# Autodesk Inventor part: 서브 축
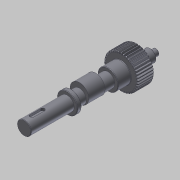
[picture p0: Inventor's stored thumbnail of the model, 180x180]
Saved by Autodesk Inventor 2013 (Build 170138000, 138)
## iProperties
Created: 2016-02
Part Number: 서브 축
Material: 강철, 연강
Document SubType Name: Modeling
Designer: mdu
Categories: <?xml version="1.0" encoding="UTF-16"?> <MemberInstance><Categories><FamilyTemplate><FamilyTemplateParameter ValueType="xs:double" Id="1" ObjectReferenceKey="da
Density: 7.86 g/cm^3
Mass: 504.229 g
Surface Area: 165.256 cm^2
Volume: 64.1513 cm^3
CustomPartVersion: 1
Author: mdu
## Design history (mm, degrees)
sketch "Sketch1"
  geometry: C1 r 21 at (0, 0)
  constraints: 1 centre point
  dimensions: "d0" = 42 diameter of C1 (= da_da)
extrude "Extrusion1" new body sketch "Sketch1" distance "d1" = 20 (= da_b); taper "d2" = 0 deg
workplane "Work Plane2"
feature "피치 지름" dims "d4" = 10, "d5" = 0
workplane "Work Plane8"
workplane "Work Plane9"
chamfer "모따기1" distance "d49" = 1; stored, may be unused: second distance "d50" = 2, angle "d51" = 45 deg
sketch "스케치3"
  geometry: C1 r 12.5 at (0, 0); 1 further point
  constraints: 1 centre point, 1 coincident
  dimensions: "d52" = 25 diameter of C1
extrude "돌출2" join sketch "스케치3" distance "d53" = 16; taper "d54" = 0 deg
sketch "스케치4"
  geometry: C1 r 8.5 at (0, 0); 1 further point
  constraints: 1 centre point, 1 coincident
  dimensions: "d55" = 17 diameter of C1
extrude "돌출3" join sketch "스케치4" distance "d56" = 103; taper "d57" = 0 deg
sketch "스케치5"
  geometry: C1 r 7.5 at (0, 0); 1 further point
  constraints: 1 centre point, 1 coincident
  dimensions: "d62" = 15 diameter of C1
extrude "돌출4" join sketch "스케치5" distance "d63" = 16; taper "d64" = 0 deg
sketch "스케치6"
  geometry: C1 r 4 at (0, 0); 1 further point
  constraints: 1 centre point, 1 coincident
  dimensions: "d65" = 8 diameter of C1
extrude "돌출5" join sketch "스케치6" distance "d66" = 7; taper "d67" = 0 deg
chamfer "모따기2" distance "d58" = 0.5; stored, may be unused: second distance "d59" = 2, angle "d60" = 45 deg
fillet "모깎기1" dims "d61" = 0.5
feature "스퍼 기어" dims "da_b" = 20, "da_d" = 40, "da_aw" = 31, "da_da" = 42, "da_df" = 37.5, "da_dw" = 40, angle "da_beta" = 0 deg, "da_lefttooth" = 0, "da_righttooth" = 0
node "작업 평면11"
sketch "스케치7"
  geometry: C1 r 8.5 at (0, 0) reference; C2 r 11.5 at (0, 3); 1 further point
  constraints: 1 centre point, 1 tangent, 1 vertical alignment
  dimensions: "d71" = 3 distance of C2.centre point (0, 0); "d72" = 23 diameter of C2 (derived)
extrude "돌출6" join sketch "스케치7" stored distance "d73" = 20; taper "d74" = 0 deg
node "작업 평면12"
sketch "스케치8"
  geometry: C1 r 12.5 at (0, 0) reference; 1 further point
extrude "돌출7" join sketch "스케치8" distance "d76" = 5; taper "d77" = 0 deg
chamfer "모따기3" distance "d78" = 0.5; stored, may be unused: second distance "d79" = 2, angle "d80" = 45 deg
sketch "스케치9"
  geometry: L1 (-8.5, 86)-(-8.5, 138.5) reference; L2 (-8, 139)-(8, 139) reference; L3 (0, 0)-(0, 139); L4 (-8.5, 115)-(0, 115); L5 (-8.5, 115)-(-8.5, 113.5); L6 (-7, 115)-(-8.5, 113.5)
  constraints: 8 end point, 4 point on line, 1 midpoint, 1 perpendicular
  dimensions: "d81" = 24 distance between parallel lines of L2 L4; "d82" = 45 deg angle of L6 L5; "d83" = 3 diameter of L5.end L4
revolve "회전1" sketch "스케치9" stored, may be unused: angle "d84" = 90 deg
sketch "스케치10"
  geometry: L1 (-8.5, 113.5)-(-7, 115) reference; L2 (-8.5, 116.5)-(-7, 115) reference; 2 further points
  constraints: 1 coincident
node "작업점1"
node "작업 평면14"
sketch "스케치11"
  geometry: L1 (8.5, 102.5)-(-8.5, 102.5) reference; L2 (0, 102.5)-(0, -36); L3 (-2.5, 93.5)-(-2.5, 80.5); L4 (2.5, 80.5)-(2.5, 93.5); L5 (-8, 103)-(8, 103) reference; A1 r 2.5 centre (0, 93.5) between (2.5, 93.5) and (-2.5, 93.5); A2 r 2.5 centre (0, 80.5) between (-2.5, 80.5) and (2.5, 80.5)
  constraints: 6 end point, 4 point on circle, 4 tangent, 2 centre point, 1 midpoint, 1 parallel, 1 perpendicular, 1 point on line, 1 vertical alignment
  dimensions: "d85" = 7 distance edge to line of A1 L5; "d86" = 18 dimension on A2 A1; "d87" = 5 distance between parallel lines of L3 L4
extrude "돌출8" cut sketch "스케치11" distance "d88" = 3; taper "d89" = 0 deg
body "Solid1"
sketch "Sketch2"
  geometry: C1 r 21 at (0, 0) reference; C2 r 20 at (0, 0)
  constraints: 1 centre point, 1 coincident
  dimensions: "d3" = 40 diameter of C2 (= da_dw)
body "Srf1"
other parameters: "d16" = 31 (= da_aw), "d17" = 0, "d34" = 4.5 deg (computed from da_z), "d39" = 0, "d41" = 0, "d43" = 31 (= da_aw), "d46" = 31 (= da_aw), "d47" = 0, "d48" = 0, "d68" = 25
